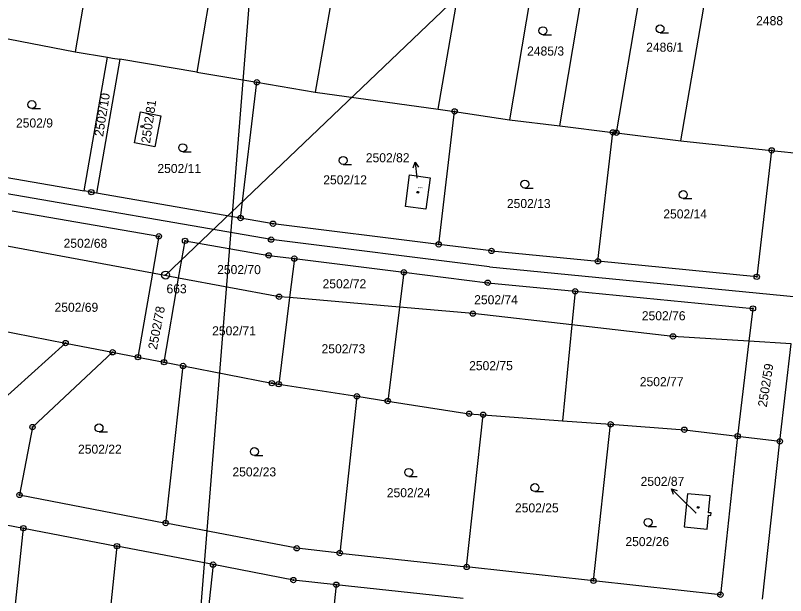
# Model space of a CAD drawing. Extents: x -755819 to -753140, y -1169796 to -1166000.
# Drawn here: x -754847.5 to -754702.7, y -1169071.2 to -1168962.2 of the extents above; entities that cross this region are included whole.
import ezdxf

# ---------------------------------------------------------------- set-up
doc = ezdxf.new("R2010")
doc.units = 0
for name, color, linetype in [('Vrstva 1', 7, 'Continuous'), ('Vrstva 12', 7, 'Continuous'), ('Vrstva 16', 7, 'Continuous'), ('Vrstva 17', 7, 'Continuous'), ('Vrstva 18', 7, 'Continuous'), ('Vrstva 19', 7, 'Continuous'), ('Vrstva 24', 7, 'Continuous'), ('Vrstva 25', 7, 'Continuous')]:
    doc.layers.add(name, color=color, linetype=linetype)

msp = doc.modelspace()

# ---------------------------------------------------------------- linework, layer by layer
at = {"layer": 'Vrstva 1'}
for p, q in [((-754780.52, -1168916.14), (-754791.18, -1168976.64)), ((-754744.35, -1168920.73), (-754754.6, -1168981.82)), ((-754745.12, -1168982.99), (-754734.85, -1168921.78)), ((-754734.49, -1168984.27), (-754724.15, -1168923.12)), ((-754722.37, -1168985.76), (-754711.97, -1168924.65)), ((-754768.05, -1168979.83), (-754760.14, -1168934.2)), ((-754830.54, -1168935.87), (-754836.29, -1168969.03)), ((-754808.02, -1168941.01), (-754813.4, -1168972.85)), ((-754853.87, -1168965.7), (-754836.29, -1168969.03)), ((-754836.29, -1168969.03), (-754830.23, -1168970.05)), ((-754834.62, -1168995.19), (-754830.23, -1168970.05)), ((-754827.87, -1168970.45), (-754832.28, -1168995.6)), ((-754830.23, -1168970.05), (-754829.25, -1168970.22)), ((-754829.25, -1168970.22), (-754827.87, -1168970.45)), ((-754813.4, -1168972.85), (-754827.87, -1168970.45)), ((-754813.4, -1168972.85), (-754802.13, -1168974.79)), ((-754805.18, -1169000.3), (-754802.13, -1168974.79)), ((-754802.13, -1168974.79), (-754791.18, -1168976.64)), ((-754791.18, -1168976.64), (-754768.05, -1168979.83)), ((-754768.05, -1168979.83), (-754764.93, -1168980.26)), ((-754825.14, -1168986.19), (-754824.01, -1168980.34)), ((-754824.01, -1168980.34), (-754820.2, -1168981.06)), ((-754820.2, -1168981.06), (-754821.33, -1168986.93)), ((-754767.93, -1169005.24), (-754764.93, -1168980.26)), ((-754764.93, -1168980.26), (-754754.6, -1168981.82)), ((-754754.6, -1168981.82), (-754745.12, -1168982.99)), ((-754745.12, -1168982.99), (-754735.17, -1168984.2)), ((-754737.98, -1169008.42), (-754735.17, -1168984.2)), ((-754735.17, -1168984.2), (-754734.49, -1168984.27)), ((-754734.49, -1168984.27), (-754722.37, -1168985.76)), ((-754722.37, -1168985.76), (-754705.32, -1168987.58)), ((-754821.33, -1168986.93), (-754825.14, -1168986.19)), ((-754705.32, -1168987.58), (-754708.12, -1169011.33)), ((-754705.32, -1168987.58), (-754697.37, -1168988.43)), ((-754856.08, -1168991.47), (-754834.62, -1168995.19)), ((-754774.19, -1168998.1), (-754773.4, -1168992.2)), ((-754773.4, -1168992.2), (-754769.53, -1168992.74)), ((-754769.53, -1168992.74), (-754770.35, -1168998.65)), ((-754799.45, -1169004.34), (-754856.67, -1168994.41)), ((-754833.26, -1168995.43), (-754834.62, -1168995.19)), ((-754832.28, -1168995.6), (-754833.26, -1168995.43)), ((-754805.18, -1169000.3), (-754832.28, -1168995.6)), ((-754770.35, -1168998.65), (-754774.19, -1168998.1)), ((-754848.15, -1168998.93), (-754820.54, -1169003.72)), ((-754799.08, -1169001.36), (-754805.18, -1169000.3)), ((-754767.93, -1169005.24), (-754799.08, -1169001.36)), ((-754820.54, -1169003.72), (-754821.74, -1169010.65)), ((-754816.83, -1169011.57), (-754815.62, -1169004.58)), ((-754815.62, -1169004.58), (-754799.89, -1169007.31)), ((-754758.37, -1169009.46), (-754799.45, -1169004.34)), ((-754821.74, -1169010.65), (-754849.46, -1169005.51)), ((-754758, -1169006.48), (-754767.93, -1169005.24)), ((-754799.89, -1169007.31), (-754795.07, -1169007.91)), ((-754758, -1169006.48), (-754737.98, -1169008.42)), ((-754795.07, -1169007.91), (-754795.99, -1169015.24)), ((-754795.07, -1169007.91), (-754774.48, -1169010.48)), ((-754708.12, -1169011.33), (-754737.98, -1169008.42)), ((-754758.37, -1169009.46), (-754700.51, -1169015.08)), ((-754821.74, -1169010.65), (-754824.48, -1169026.43)), ((-754816.83, -1169011.57), (-754821.74, -1169010.65)), ((-754819.57, -1169027.38), (-754816.83, -1169011.57)), ((-754797.94, -1169015.07), (-754816.83, -1169011.57)), ((-754774.48, -1169010.48), (-754775.3, -1169017.04)), ((-754774.48, -1169010.48), (-754758.7, -1169012.44)), ((-754758.7, -1169012.44), (-754742.27, -1169014.04)), ((-754742.27, -1169014.04), (-754742.89, -1169020.36)), ((-754742.27, -1169014.04), (-754708.84, -1169017.29)), ((-754795.99, -1169015.24), (-754798.01, -1169031.51)), ((-754795.99, -1169015.24), (-754797.94, -1169015.07)), ((-754775.3, -1169017.04), (-754795.99, -1169015.24)), ((-754775.3, -1169017.04), (-754777.5, -1169034.69)), ((-754761.5, -1169018.24), (-754775.3, -1169017.04)), ((-754708.84, -1169017.29), (-754709.58, -1169023.44)), ((-754742.89, -1169020.36), (-754761.5, -1169018.24)), ((-754742.89, -1169020.36), (-754744.64, -1169038.37)), ((-754723.87, -1169022.52), (-754742.89, -1169020.36)), ((-754852.54, -1169020.99), (-754838.09, -1169023.79)), ((-754709.58, -1169023.44), (-754723.87, -1169022.52)), ((-754709.58, -1169023.44), (-754711.72, -1169041.28)), ((-754701.62, -1169023.95), (-754709.58, -1169023.44)), ((-754838.09, -1169023.79), (-754865.71, -1169048.69)), ((-754838.09, -1169023.79), (-754829.25, -1169025.51)), ((-754703.77, -1169042.24), (-754701.62, -1169023.95)), ((-754829.25, -1169025.51), (-754844.3, -1169039.57)), ((-754829.25, -1169025.51), (-754824.48, -1169026.43)), ((-754824.48, -1169026.43), (-754819.57, -1169027.38)), ((-754819.57, -1169027.38), (-754816, -1169028.08)), ((-754819.26, -1169057.61), (-754816, -1169028.08)), ((-754816, -1169028.08), (-754799.31, -1169031.31)), ((-754799.31, -1169031.31), (-754798.01, -1169031.51)), ((-754798.01, -1169031.51), (-754783.32, -1169033.79)), ((-754783.32, -1169033.79), (-754786.53, -1169063.23)), ((-754783.32, -1169033.79), (-754777.5, -1169034.69)), ((-754777.5, -1169034.69), (-754762.19, -1169037.06)), ((-754762.67, -1169065.84), (-754759.56, -1169037.25)), ((-754762.19, -1169037.06), (-754759.56, -1169037.25)), ((-754759.56, -1169037.25), (-754744.64, -1169038.37)), ((-754744.64, -1169038.37), (-754735.61, -1169039.04)), ((-754738.82, -1169068.45), (-754735.61, -1169039.04)), ((-754735.61, -1169039.04), (-754721.73, -1169040.07)), ((-754844.3, -1169039.57), (-754846.75, -1169052.33)), ((-754721.73, -1169040.07), (-754711.72, -1169041.28)), ((-754711.72, -1169041.28), (-754714.96, -1169071.06)), ((-754711.72, -1169041.28), (-754703.77, -1169042.24)), ((-754707.01, -1169071.93), (-754703.77, -1169042.24)), ((-754846.75, -1169052.33), (-754819.26, -1169057.61)), ((-754721.16, -1169052.09), (-754721.77, -1169058.34)), ((-754716.86, -1169052.5), (-754721.16, -1169052.09)), ((-754717.17, -1169055.67), (-754716.86, -1169052.5)), ((-754860.74, -1169055.75), (-754846.01, -1169058.57)), ((-754717.47, -1169058.75), (-754717.21, -1169056.12)), ((-754717.21, -1169056.12), (-754716.76, -1169056.16)), ((-754716.72, -1169055.71), (-754717.17, -1169055.67)), ((-754716.76, -1169056.16), (-754716.72, -1169055.71)), ((-754794.61, -1169062.35), (-754819.26, -1169057.61)), ((-754848.96, -1169086.48), (-754846.01, -1169058.57)), ((-754846.01, -1169058.57), (-754828.43, -1169061.94)), ((-754721.77, -1169058.34), (-754717.47, -1169058.75)), ((-754828.43, -1169061.94), (-754831.38, -1169089.83)), ((-754810.36, -1169065.41), (-754828.43, -1169061.94)), ((-754786.53, -1169063.23), (-754794.61, -1169062.35)), ((-754786.53, -1169063.23), (-754762.67, -1169065.84)), ((-754810.36, -1169065.41), (-754813.31, -1169093.27)), ((-754795.24, -1169068.31), (-754810.36, -1169065.41)), ((-754738.82, -1169068.45), (-754762.67, -1169065.84)), ((-754787.18, -1169069.2), (-754795.24, -1169068.31)), ((-754787.18, -1169069.2), (-754790.21, -1169097)), ((-754763.32, -1169071.8), (-754787.18, -1169069.2)), ((-754714.96, -1169071.06), (-754738.82, -1169068.45))]:
    msp.add_line(p, q, dxfattribs=at)
at = {"layer": 'Vrstva 12'}
for p, q in [((-754645.34, -1168845.03), (-754819.27, -1169011.01)), ((-754815.14, -1169104.59), (-754797.68, -1168887.42))]:
    msp.add_line(p, q, dxfattribs=at)
at = {"layer": 'Vrstva 16'}
for p, q in [((-754772.33, -1168989.81), (-754772.05, -1168992.8)), ((-754724.15, -1169051.15), (-754722.03, -1169053.27)), ((-754719.53, -1169055.76), (-754722.03, -1169053.27))]:
    msp.add_line(p, q, dxfattribs=at)
for points in [[(-754772.73, -1168990.85), (-754772.33, -1168989.81), (-754771.74, -1168990.76)], [(-754723.8, -1169052.21), (-754724.15, -1169051.15), (-754723.09, -1169051.5)]]:
    msp.add_lwpolyline(points, dxfattribs=at)
at = {"layer": 'Vrstva 24'}
for centre, radius in [((-754802.13, -1168974.79), 0.5), ((-754802.13, -1168974.79), 0.1), ((-754764.93, -1168980.26), 0.5), ((-754764.93, -1168980.26), 0.1), ((-754735.17, -1168984.2), 0.5), ((-754735.17, -1168984.2), 0.1), ((-754734.49, -1168984.27), 0.5), ((-754734.49, -1168984.27), 0.1), ((-754705.32, -1168987.58), 0.5), ((-754705.32, -1168987.58), 0.1), ((-754833.26, -1168995.43), 0.5), ((-754833.26, -1168995.43), 0.1), ((-754805.18, -1169000.3), 0.5), ((-754805.18, -1169000.3), 0.1), ((-754799.08, -1169001.36), 0.5), ((-754799.08, -1169001.36), 0.1), ((-754820.54, -1169003.72), 0.5), ((-754820.54, -1169003.72), 0.1), ((-754815.62, -1169004.58), 0.5), ((-754815.62, -1169004.58), 0.1), ((-754799.45, -1169004.34), 0.5), ((-754799.45, -1169004.34), 0.1), ((-754767.93, -1169005.24), 0.5), ((-754767.93, -1169005.24), 0.1), ((-754758, -1169006.48), 0.5), ((-754799.89, -1169007.31), 0.5), ((-754799.89, -1169007.31), 0.1), ((-754795.07, -1169007.91), 0.5), ((-754758, -1169006.48), 0.1), ((-754795.07, -1169007.91), 0.1), ((-754737.98, -1169008.42), 0.5), ((-754737.98, -1169008.42), 0.1), ((-754819.27, -1169011.01), 0.75), ((-754774.48, -1169010.48), 0.5), ((-754774.48, -1169010.48), 0.1), ((-754819.27, -1169011.01), 0.1), ((-754708.12, -1169011.33), 0.5), ((-754708.12, -1169011.33), 0.1), ((-754758.7, -1169012.44), 0.5), ((-754758.7, -1169012.44), 0.1), ((-754797.94, -1169015.07), 0.5), ((-754742.27, -1169014.04), 0.5), ((-754742.27, -1169014.04), 0.1), ((-754797.94, -1169015.07), 0.1), ((-754708.84, -1169017.29), 0.5), ((-754708.84, -1169017.29), 0.1), ((-754761.5, -1169018.24), 0.5), ((-754761.5, -1169018.24), 0.1), ((-754723.87, -1169022.52), 0.5), ((-754838.09, -1169023.79), 0.5), ((-754723.87, -1169022.52), 0.1), ((-754838.09, -1169023.79), 0.1), ((-754829.25, -1169025.51), 0.5), ((-754829.25, -1169025.51), 0.1), ((-754824.48, -1169026.43), 0.5), ((-754824.48, -1169026.43), 0.1), ((-754819.57, -1169027.38), 0.5), ((-754819.57, -1169027.38), 0.1), ((-754816, -1169028.08), 0.5), ((-754816, -1169028.08), 0.1), ((-754799.31, -1169031.31), 0.5), ((-754799.31, -1169031.31), 0.1), ((-754798.01, -1169031.51), 0.5), ((-754798.01, -1169031.51), 0.1), ((-754783.32, -1169033.79), 0.5), ((-754783.32, -1169033.79), 0.1), ((-754777.5, -1169034.69), 0.5), ((-754777.5, -1169034.69), 0.1), ((-754762.19, -1169037.06), 0.5), ((-754762.19, -1169037.06), 0.1), ((-754759.56, -1169037.25), 0.5), ((-754759.56, -1169037.25), 0.1), ((-754844.3, -1169039.57), 0.5), ((-754735.61, -1169039.04), 0.5), ((-754735.61, -1169039.04), 0.1), ((-754844.3, -1169039.57), 0.1), ((-754721.73, -1169040.07), 0.5), ((-754721.73, -1169040.07), 0.1), ((-754711.72, -1169041.28), 0.5), ((-754711.72, -1169041.28), 0.1), ((-754703.77, -1169042.24), 0.5), ((-754703.77, -1169042.24), 0.1), ((-754846.75, -1169052.33), 0.5), ((-754846.75, -1169052.33), 0.1), ((-754846.01, -1169058.57), 0.5), ((-754819.26, -1169057.61), 0.5), ((-754819.26, -1169057.61), 0.1), ((-754846.01, -1169058.57), 0.1), ((-754828.43, -1169061.94), 0.5), ((-754828.43, -1169061.94), 0.1), ((-754794.61, -1169062.35), 0.5), ((-754794.61, -1169062.35), 0.1), ((-754786.53, -1169063.23), 0.5), ((-754786.53, -1169063.23), 0.1), ((-754810.36, -1169065.41), 0.5), ((-754810.36, -1169065.41), 0.1), ((-754762.67, -1169065.84), 0.5), ((-754762.67, -1169065.84), 0.1), ((-754795.24, -1169068.31), 0.5), ((-754795.24, -1169068.31), 0.1), ((-754738.82, -1169068.45), 0.5), ((-754738.82, -1169068.45), 0.1), ((-754787.18, -1169069.2), 0.5), ((-754787.18, -1169069.2), 0.1), ((-754714.96, -1169071.06), 0.5), ((-754714.96, -1169071.06), 0.1)]:
    msp.add_circle(centre, radius, dxfattribs=at)
at = {"layer": 'Vrstva 25'}
for p, q in [((-754726.31, -1168965.49), (-754724.71, -1168965.49)), ((-754748.32, -1168965.84), (-754746.72, -1168965.84)), ((-754844.43, -1168979.72), (-754842.83, -1168979.72)), ((-754816.06, -1168987.82), (-754814.46, -1168987.82)), ((-754785.89, -1168990.22), (-754784.29, -1168990.22)), ((-754751.73, -1168994.67), (-754750.13, -1168994.67)), ((-754721.94, -1168996.63), (-754720.34, -1168996.63)), ((-754831.8, -1169040.47), (-754830.2, -1169040.47)), ((-754802.58, -1169044.92), (-754800.98, -1169044.92)), ((-754773.55, -1169048.84), (-754771.95, -1169048.84)), ((-754749.83, -1169051.69), (-754748.23, -1169051.69)), ((-754728.55, -1169058.23), (-754726.95, -1169058.23))]:
    msp.add_line(p, q, dxfattribs=at)
for centre, radius in [((-754726.31, -1168964.74), 0.75), ((-754748.32, -1168965.09), 0.75), ((-754844.43, -1168978.97), 0.75), ((-754823.73, -1168983.1), 0.175), ((-754816.06, -1168987.07), 0.75), ((-754785.89, -1168989.47), 0.75), ((-754751.73, -1168993.92), 0.75), ((-754771.83, -1168995.45), 0.175), ((-754721.94, -1168995.88), 0.75), ((-754831.8, -1169039.72), 0.75), ((-754802.58, -1169044.17), 0.75), ((-754773.55, -1169048.09), 0.75), ((-754749.83, -1169050.94), 0.75), ((-754719.13, -1169054.66), 0.175), ((-754728.55, -1169057.48), 0.75)]:
    msp.add_circle(centre, radius, dxfattribs=at)

# ---------------------------------------------------------------- texts
at = {"layer": 'Vrstva 16'}
for s, p in [('2502/82', (-754781.63, -1168989.81)), ('2502/87', (-754729.96, -1169050.62))]:
    msp.add_text(s, height=1.7, dxfattribs=at).set_placement(p)
at = {"layer": 'Vrstva 17'}
msp.add_text('663', height=1.7, dxfattribs=at).set_placement((-754819.11, -1169014.43))
at = {"layer": 'Vrstva 18'}
for s, p in [('2488', (-754708.23, -1168964.06)), ('2485/3', (-754751.3, -1168969.76)), ('2486/1', (-754728.91, -1168969.04)), ('2502/9', (-754847.41, -1168983.28)), ('2502/11', (-754820.82, -1168991.83)), ('2502/12', (-754789.63, -1168993.96)), ('2502/13', (-754755.1, -1168998.41)), ('2502/14', (-754725.69, -1169000.37)), ('2502/68', (-754838.46, -1169005.88)), ('2502/70', (-754809.58, -1169010.83)), ('2502/72', (-754789.76, -1169013.49)), ('2502/74', (-754761.25, -1169016.49)), ('2502/69', (-754840.16, -1169017.91)), ('2502/76', (-754729.73, -1169019.5)), ('2502/71', (-754810.52, -1169022.33)), ('2502/73', (-754789.95, -1169025.7)), ('2502/75', (-754762.2, -1169028.88)), ('2502/77', (-754730.11, -1169031.89)), ('2502/22', (-754835.74, -1169044.57)), ('2502/23', (-754806.71, -1169048.84)), ('2502/24', (-754777.68, -1169052.75)), ('2502/25', (-754753.58, -1169055.6)), ('2502/26', (-754732.82, -1169061.94))]:
    msp.add_text(s, height=1.7, dxfattribs=at).set_placement(p)
for s, rotation, p in [('2502/10', 80.8443, (-754831.04, -1168985.07)), ('2502/78', 79.1828, (-754820.92, -1169025.11)), ('2502/59', 81.0162, (-754706.25, -1169035.9))]:
    msp.add_text(s, height=1.7, rotation=rotation, dxfattribs=at).set_placement(p)
at = {"layer": 'Vrstva 19'}
msp.add_text('2502/81', height=1.7, rotation=81.7038, dxfattribs=at).set_placement((-754822.21, -1168986.34))
for s, height, p in [('2502/82', 0.2, (-754771.84, -1168994.73)), ('2502/87', 0.1, (-754719.83, -1169055.76))]:
    msp.add_text(s, height=height, dxfattribs=at).set_placement(p)

doc.saveas('drawing.dxf')
